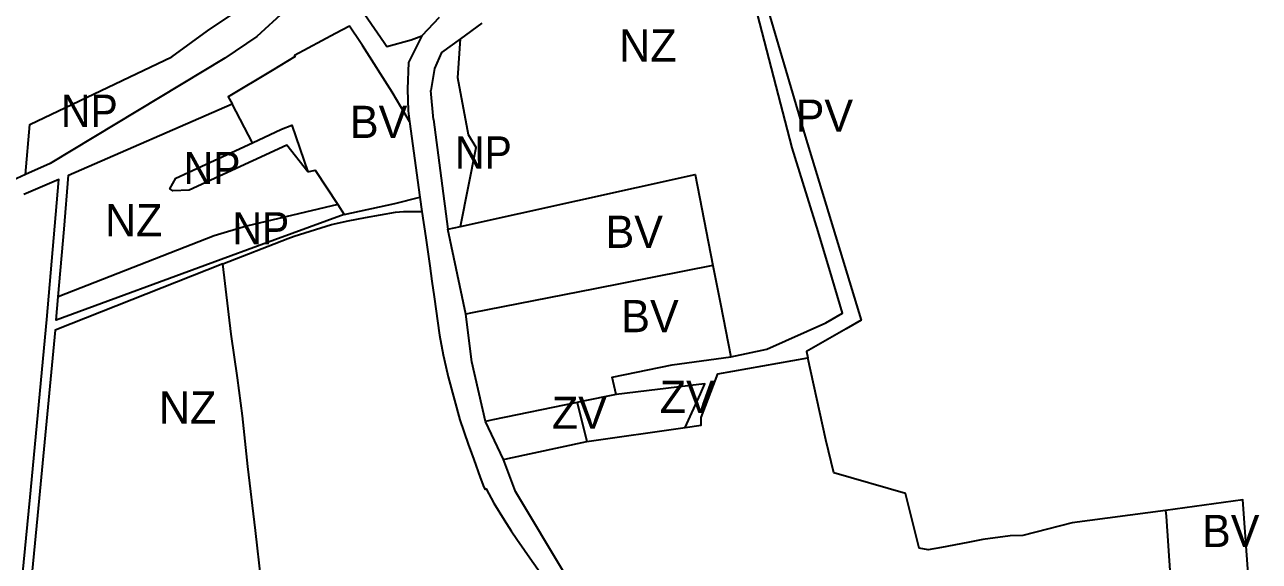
# Model space of a CAD drawing. Extents: x -650451 to -642268, y -1075216 to -1066610.
# Drawn here: x -643995 to -643420, y -1069881 to -1069631 of the extents above; entities that cross this region are included whole.
import ezdxf

# ---------------------------------------------------------------- set-up
doc = ezdxf.new("R2010")
doc.units = 0
doc.header["$LTSCALE"] = 6
doc.layers.add('1', color=7, linetype='Continuous', lineweight=35)
doc.layers.add('2', color=7, linetype='Continuous')
doc.layers.add('3', color=7, linetype='Continuous')

msp = doc.modelspace()

# ---------------------------------------------------------------- linework, layer by layer
at = {"layer": '1'}
for p, q in [((-643801.71, -1069628.02), (-643809.91, -1069636.52)), ((-643781.95, -1069630.63), (-643791.77, -1069637.88)), ((-643809.91, -1069636.52), (-643816.12, -1069649.03)), ((-643804.44, -1069675.58), (-643805.65, -1069661.94)), ((-643888.63, -1069686.33), (-643898.1, -1069668.26)), ((-643816.18, -1069671.49), (-643815.53, -1069676.49)), ((-643815.53, -1069676.49), (-643810.77, -1069711.69)), ((-643804.44, -1069675.58), (-643797.75, -1069726.51)), ((-643810.77, -1069711.69), (-643809.85, -1069718.31)), ((-643849.02, -1069715.11), (-643846.01, -1069719.71)), ((-643809.85, -1069718.31), (-643808.05, -1069730.51)), ((-643808.05, -1069730.51), (-643806.11, -1069743.61)), ((-643797.75, -1069726.51), (-643791.88, -1069725.25)), ((-643789.3, -1069766.05), (-643797.75, -1069726.51)), ((-643806.11, -1069743.61), (-643805.14, -1069750.81)), ((-643797.65, -1069795.29), (-643794.68, -1069806.22)), ((-643737.47, -1069807.24), (-643733.02, -1069825.4)), ((-643771.78, -1069833.76), (-643780.19, -1069816.07)), ((-643733.02, -1069825.4), (-643687.2, -1069818.8)), ((-643785.66, -1069833.72), (-643782.76, -1069842.22)), ((-643782.76, -1069842.22), (-643780.9, -1069846.66))]:
    msp.add_line(p, q, dxfattribs=at)
for points in [[(-643666.98, -1069562.22), (-643665.49, -1069567.27), (-643631.37, -1069683.21), (-643607.44, -1069761.72), (-643605.24, -1069768.92), (-643612.22, -1069772.9), (-643630.77, -1069783.44), (-643630.05, -1069786.46)], [(-643665.92, -1069785.96), (-643649.25, -1069782.43), (-643621.71, -1069770.11), (-643613.9, -1069765.6), (-643619, -1069748.93), (-643625.33, -1069727.69), (-643637.36, -1069688.73), (-643668.5, -1069568.92), (-643669.73, -1069564.16)], [(-643994.36, -1069701.05), (-643992.34, -1069677.76), (-643926.229, -1069646.367), (-643909.616, -1069634.267), (-643895.951, -1069625.069), (-643870.697, -1069601.241)], [(-643870.697, -1069601.241), (-643863.92, -1069613.9), (-643870.44, -1069613.56), (-643872.55, -1069620.75), (-643873.82, -1069625.05), (-643886.62, -1069636.87), (-643901.55, -1069646.92), (-643982.84, -1069695.93), (-643994.36, -1069701.05)], [(-643837.72, -1069604.62), (-643847.68, -1069608.59), (-643848.42, -1069608.88), (-643827.36, -1069639.65), (-643826.08, -1069641.51), (-643814.83, -1069638.49), (-643809.91, -1069636.52)], [(-643815.53, -1069676.49), (-643823.72, -1069662.84), (-643837.42, -1069641.07), (-643838.44, -1069639.59), (-643843.55, -1069632.12), (-643850.07, -1069635.49), (-643869.1, -1069645.78), (-643868.85, -1069646.21), (-643879.6, -1069652.65), (-643900.07, -1069664.92), (-643898.1, -1069668.26)], [(-643791.77, -1069637.88), (-643800.73, -1069644.37), (-643803.94, -1069651.83), (-643805.65, -1069661.94)], [(-643791.88, -1069725.25), (-643784.59, -1069688.47), (-643788.14, -1069682.71), (-643793.09, -1069656.07), (-643791.77, -1069637.88)], [(-643816.12, -1069649.03), (-643816.54, -1069661.32), (-643816.18, -1069671.49)], [(-643979.17, -1069758.05), (-643976.33, -1069726.63), (-643974.4, -1069701.49), (-643898.1, -1069668.26)], [(-643888.63, -1069686.33), (-643875.12, -1069680.07), (-643870.37, -1069678.12), (-643862.96, -1069699.89)], [(-643862.96, -1069699.89), (-643872.67, -1069687.46), (-643918.15, -1069708.43), (-643925.71, -1069708.74), (-643927.13, -1069707.8), (-643924.39, -1069702.76), (-643888.63, -1069686.33)], [(-643994.36, -1069701.05), (-644018.79, -1069712.33), (-644022.04, -1069713.81), (-644052.45, -1069724.5), (-644077.42, -1069731.58), (-644117.03, -1069742.82), (-644146.79, -1069751.26), (-644159.71, -1069754.93), (-644171.84, -1069758.14), (-644256.15, -1069780.42), (-644322.59, -1069801.71), (-644360.34, -1069814.36), (-644413.11, -1069832.07), (-644417.59, -1069832.48)], [(-643862.96, -1069699.89), (-643859.47, -1069699.1), (-643849.02, -1069715.11)], [(-643791.88, -1069725.25), (-643682.61, -1069701.16), (-643674.3, -1069743.53)], [(-644050.12, -1070033.64), (-644053.18, -1070030.57), (-644051.913, -1070029.549), (-644009.95, -1069995.74), (-644006.96, -1069990.34), (-644005.06, -1069981.28), (-644003.06, -1069964.06), (-644000.52, -1069937.19), (-643992.27, -1069851.31), (-643984.44, -1069768.58), (-643978.85, -1069703.4), (-643995.17, -1069710.42)], [(-643846.01, -1069719.71), (-643822.49, -1069714.53), (-643810.77, -1069711.69)], [(-643849.02, -1069715.11), (-643891.46, -1069725.11), (-643906.6, -1069729.62), (-643979.17, -1069758.05)], [(-643902.55, -1069742.76), (-643872.27, -1069730.92), (-643869.29, -1069729.75), (-643851.98, -1069724.37), (-643844.1, -1069722.64), (-643836.08, -1069721.14), (-643822.16, -1069718.6), (-643818.38, -1069718.34), (-643809.85, -1069718.31)], [(-643846.01, -1069719.71), (-643886.39, -1069734.49), (-643903.24, -1069740.66), (-643980.16, -1069768.97), (-643979.17, -1069758.05)], [(-643902.55, -1069742.76), (-643980.59, -1069773.52), (-643987.99, -1069851.72), (-643997.58, -1069951.51), (-643998.84, -1069964.53), (-644000.57, -1069982.55), (-644002.61, -1069991.44), (-644004.06, -1069994.59)], [(-643918.88, -1069986.82), (-643918.89, -1069986.45), (-643919.56, -1069967.29), (-643919.32, -1069950.49), (-643919.43, -1069945.16), (-643919.45, -1069944.39), (-643919.73, -1069930.79), (-643919.78, -1069928.09), (-643903.94, -1069925.59), (-643896.57, -1069921.83), (-643883.81, -1069913.64), (-643882.43, -1069913.54), (-643883.23, -1069902.88), (-643883.82, -1069902.98), (-643884.67, -1069890.08), (-643887.35, -1069866.84), (-643890.8, -1069837), (-643893.29, -1069813.42), (-643895.71, -1069795.81), (-643898.69, -1069775.37), (-643902.55, -1069742.76)], [(-643674.3, -1069743.53), (-643729.34, -1069754.3), (-643764.94, -1069761.27), (-643786.35, -1069765.46), (-643789.3, -1069766.05)], [(-643674.3, -1069743.53), (-643670.76, -1069761.28), (-643665.92, -1069785.96)], [(-643805.14, -1069750.81), (-643804.15, -1069758.03), (-643801.59, -1069775.89)], [(-643780.19, -1069816.07), (-643786.64, -1069788.25), (-643789.3, -1069766.05)], [(-643801.59, -1069775.89), (-643799.88, -1069785.02), (-643799.49, -1069787.14), (-643797.65, -1069795.29)], [(-643719.42, -1069803.49), (-643721.26, -1069795.38), (-643693.34, -1069789.76), (-643665.92, -1069785.96)], [(-643687.2, -1069818.8), (-643679.72, -1069817.72), (-643679.73, -1069814.23), (-643672, -1069793.92), (-643630.05, -1069786.46)], [(-643463.51, -1069857.44), (-643507.1, -1069863.33), (-643530.01, -1069869.17), (-643535.83, -1069869.23), (-643548.67, -1069871.08), (-643555.57, -1069872.38), (-643567.91, -1069874.7), (-643574.05, -1069875.85), (-643578.28, -1069874.97), (-643584.63, -1069849.66), (-643618, -1069840.01), (-643621.78, -1069824.57), (-643630.05, -1069786.46)], [(-643687.2, -1069818.8), (-643680.15, -1069803.22), (-643678.02, -1069798.52), (-643680.83, -1069798.86), (-643719.42, -1069803.49)], [(-643719.42, -1069803.49), (-643735.51, -1069806.83), (-643737.47, -1069807.24)], [(-643794.68, -1069806.22), (-643792.21, -1069815.34), (-643788.28, -1069826.69), (-643786.7, -1069830.87), (-643785.66, -1069833.72)], [(-643737.47, -1069807.24), (-643776.76, -1069815.36), (-643778.23, -1069815.67), (-643780.19, -1069816.07)], [(-643771.78, -1069833.76), (-643769.82, -1069833.34), (-643733.02, -1069825.4)], [(-643742.29, -1069888.47), (-643766.19, -1069848.7), (-643771.78, -1069833.76)], [(-643780.9, -1069846.66), (-643780.36, -1069847.67), (-643779.92, -1069847.44), (-643776.35, -1069854.14)], [(-643776.35, -1069854.14), (-643771.54, -1069861.84), (-643768.32, -1069867), (-643765.54, -1069870.9), (-643758.44, -1069881.07)], [(-643422.204, -1069927.68), (-643427.6, -1069852.59), (-643463.51, -1069857.44)], [(-643463.51, -1069857.44), (-643463.31, -1069860.18), (-643461.326, -1069887.84)], [(-643758.44, -1069881.07), (-643755.12, -1069885.83), (-643743.79, -1069905.36)]]:
    msp.add_lwpolyline(points, dxfattribs=at)

# ---------------------------------------------------------------- texts
at = {"layer": '2'}
for s, p in [('NZ', (-643717.979, -1069648.568)), ('PV', (-643635.787, -1069681.241)), ('BV', (-643843.336, -1069684.11)), ('NZ', (-643957.378, -1069729.846)), ('BV', (-643716.977, -1069774.524)), ('NZ', (-643932.256, -1069817.034)), ('ZV', (-643749.3, -1069819.494))]:
    msp.add_text(s, height=15, dxfattribs=at).set_placement(p)
at = {"layer": '2', "width": 0.95}
for p in [(-643794.415, -1069698.367), (-643920.764, -1069705.571), (-643898.043, -1069733.649)]:
    msp.add_text('NP', height=15, dxfattribs=at).set_placement(p)
at = {"layer": '3', "width": 0.95}
msp.add_text('NP', height=15, dxfattribs=at).set_placement((-643977.889, -1069678.943))
at = {"layer": '3'}
for s, p in [('BV', (-643724.318, -1069735.287)), ('ZV', (-643699.048, -1069812.143)), ('BV', (-643446.564, -1069874.533))]:
    msp.add_text(s, height=15, dxfattribs=at).set_placement(p)

doc.saveas('drawing.dxf')
